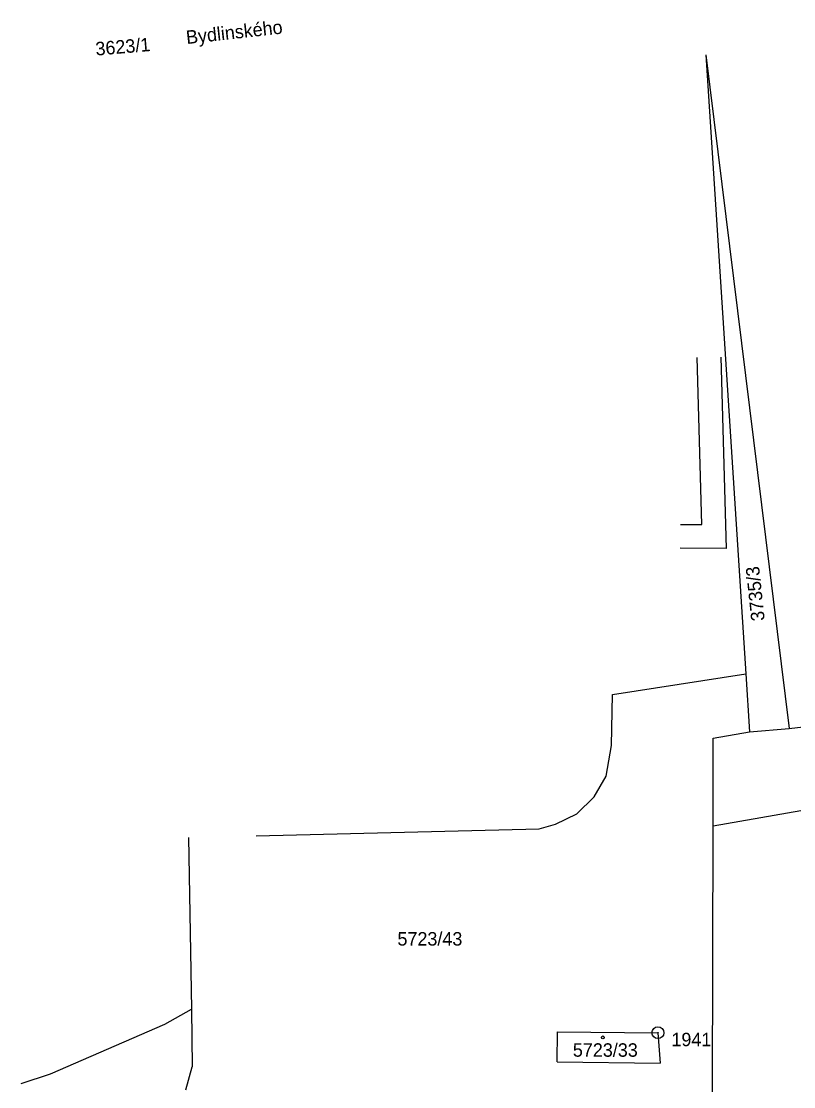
# Model space of a CAD drawing. Extents: x -735092 to -733385, y -1122435 to -1118992.
# Drawn here: x -734650.7 to -734552.9, y -1120662.2 to -1120527.4 of the extents above; entities that cross this region are included whole.
import ezdxf

# ---------------------------------------------------------------- set-up
doc = ezdxf.new("R2010")
doc.units = 0
for name, color, linetype in [('Vrstva 1', 7, 'Continuous'), ('Vrstva 15', 7, 'Continuous'), ('Vrstva 17', 7, 'Continuous'), ('Vrstva 18', 7, 'Continuous'), ('Vrstva 19', 7, 'Continuous'), ('Vrstva 25', 7, 'Continuous'), ('Vrstva 27', 7, 'Continuous')]:
    doc.layers.add(name, color=color, linetype=linetype)

msp = doc.modelspace()

# ---------------------------------------------------------------- linework, layer by layer
at = {"layer": 'Vrstva 1'}
for points in [[(-734564.06, -1120531.63), (-734558.99, -1120609.99)], [(-734564.06, -1120531.63), (-734553.54, -1120616.89)], [(-734553.54, -1120616.89), (-734438.1, -1120603.16)], [(-734575.89, -1120612.58), (-734558.99, -1120609.99)], [(-734558.99, -1120609.99), (-734558.52, -1120617.32)], [(-734575.98, -1120619.02), (-734575.89, -1120612.58)], [(-734558.52, -1120617.32), (-734553.54, -1120616.89)], [(-734563.14, -1120629.2), (-734563.12, -1120618.12)], [(-734563.12, -1120618.12), (-734558.52, -1120617.32)], [(-734576.69, -1120622.92), (-734575.98, -1120619.02)], [(-734578.2, -1120625.53), (-734576.69, -1120622.92)], [(-734580.37, -1120627.68), (-734578.2, -1120625.53)], [(-734563.14, -1120629.2), (-734546, -1120626.19)], [(-734583.08, -1120629.01), (-734580.37, -1120627.68)], [(-734585.15, -1120629.59), (-734583.08, -1120629.01)], [(-734620.94, -1120630.46), (-734585.15, -1120629.59)], [(-734563.21, -1120662.86), (-734563.14, -1120629.2)], [(-734629.51, -1120630.67), (-734629.15, -1120652.39)], [(-734632.52, -1120654.31), (-734629.15, -1120652.39)], [(-734629.15, -1120652.39), (-734629.03, -1120659.7)], [(-734646.97, -1120660.6), (-734632.52, -1120654.31)], [(-734582.89, -1120659.06), (-734582.84, -1120655.26)], [(-734582.84, -1120655.26), (-734570.13, -1120655.38)], [(-734570.13, -1120655.38), (-734569.83, -1120659.22)], [(-734629.86, -1120662.61), (-734629.03, -1120659.7)], [(-734582.89, -1120659.06), (-734569.83, -1120659.22)], [(-734650.66, -1120661.81), (-734646.97, -1120660.6)]]:
    msp.add_lwpolyline(points, dxfattribs=at)
at = {"layer": 'Vrstva 25'}
for centre, radius in [((-734570.13, -1120655.38), 0.75), ((-734577.08, -1120655.97), 0.175), ((-734570.13, -1120655.38), 0.032)]:
    msp.add_circle(centre, radius, dxfattribs=at)
at = {"layer": 'Vrstva 27'}
for points in [[(-734564.57, -1120591.09), (-734565.17, -1120569.93)], [(-734562.17, -1120569.88), (-734561.48, -1120594.11)], [(-734567.26, -1120591.07), (-734564.57, -1120591.09)], [(-734561.48, -1120594.11), (-734567.29, -1120594.07)]]:
    msp.add_lwpolyline(points, dxfattribs=at)

# ---------------------------------------------------------------- texts
at = {"layer": 'Vrstva 15'}
msp.add_text('Bydlinského', height=1.69999, rotation=6.30005, dxfattribs=at).set_placement((-734629.724, -1120530.29))
at = {"layer": 'Vrstva 17'}
msp.add_text('1941', height=1.7, dxfattribs=at).set_placement((-734568.42, -1120657.09))
at = {"layer": 'Vrstva 18'}
for s, rotation, p in [('3623/1', 4.80004, (-734641.208, -1120531.744)), ('3735/3', 96.00076, (-734556.609, -1120603.203))]:
    msp.add_text(s, height=1.7, rotation=rotation, dxfattribs=at).set_placement(p)
msp.add_text('5723/43', height=1.7, dxfattribs=at).set_placement((-734603.08, -1120644.35))
at = {"layer": 'Vrstva 19'}
msp.add_text('5723/33', height=1.7, dxfattribs=at).set_placement((-734580.89, -1120658.42))

doc.saveas('drawing.dxf')
